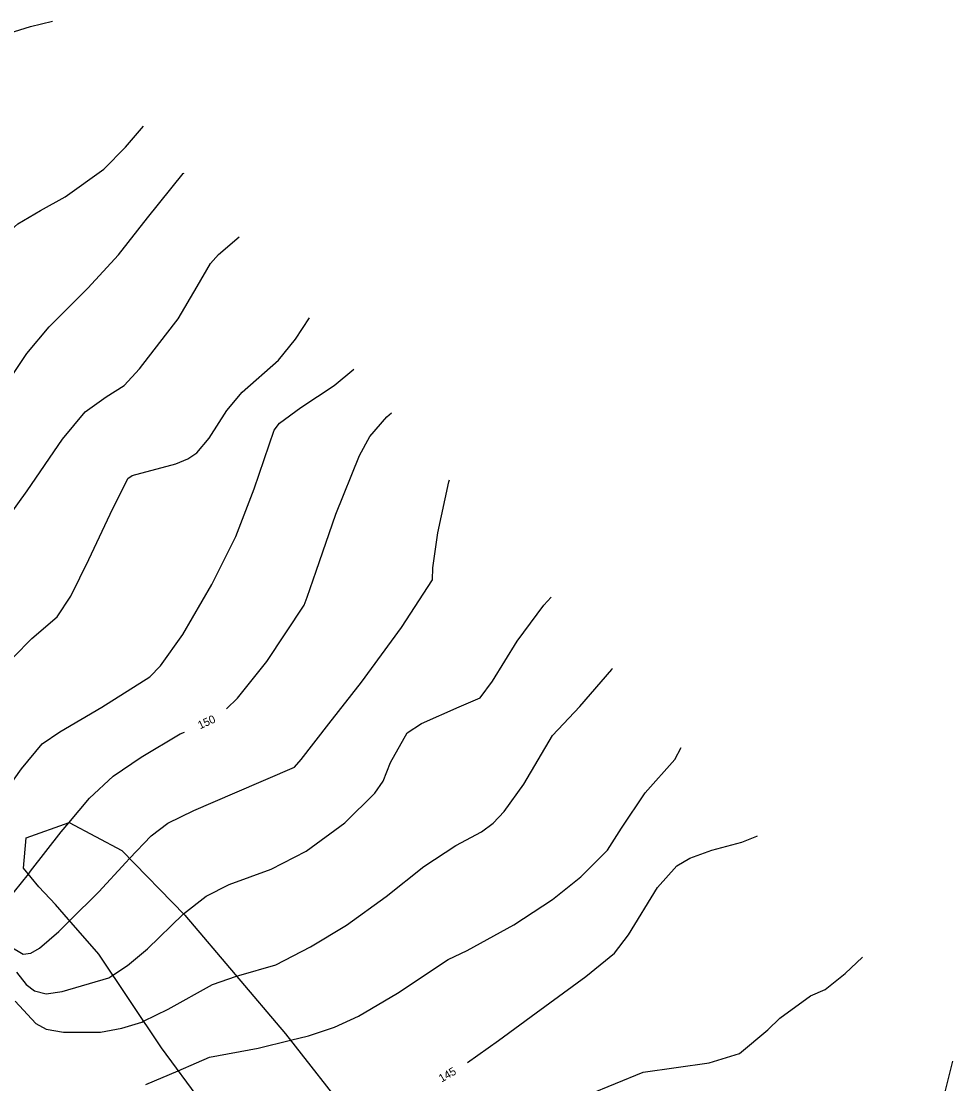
# Model space of a CAD drawing. Extents: x 1467615 to 2003689, y 770235 to 1108726.
# Drawn here: x 2000704.8 to 2000937.1, y 773522.7 to 773787.7 of the extents above; entities that cross this region are included whole.
import ezdxf

# ---------------------------------------------------------------- set-up
doc = ezdxf.new("R2010")
doc.units = 0
for name, color, linetype in [('RD_DTM_Major1', 7, 'Continuous'), ('RD_DTM_Major1_Lbl', 7, 'Continuous'), ('RD_DTM_Major2', 7, 'Continuous'), ('RD_DTM_Minor1', 7, 'Continuous'), ('RD_DTM_Minor2', 7, 'Continuous'), ('RD_DTM_Obscure', 7, 'Continuous')]:
    doc.layers.add(name, color=color, linetype=linetype)

msp = doc.modelspace()

# ---------------------------------------------------------------- linework, layer by layer
at = {"layer": 'RD_DTM_Major1'}
for points in [[(2000670.71, 773684.15), (2000672.17, 773685.91), (2000676.92, 773693.59), (2000683.08, 773706.51), (2000686.44, 773711.87), (2000690.3, 773716.17), (2000695.1, 773720.9), (2000696.9, 773724.25), (2000699.75, 773732.32), (2000701.53, 773734.98), (2000703.98, 773737.23), (2000709.63, 773740.52), (2000715.78, 773743.93), (2000725.45, 773750.81), (2000730.87, 773756.33), (2000735.33, 773761.55)], [(2000756.03, 773616.27), (2000758.78, 773618.87), (2000766.05, 773628.08), (2000775.35, 773642.1), (2000776.13, 773644.05), (2000778.35, 773650.59), (2000783.3, 773664.81), (2000789.2, 773679.42), (2000791.78, 773684.13), (2000796.03, 773689.04), (2000797.18, 773690.06)], [(2000716.71, 773587.83), (2000721.89, 773593.94), (2000727.8, 773599.46), (2000734.75, 773604.17), (2000744.49, 773609.96), (2000745.51, 773610.43)], [(2000816.14, 773528.05), (2000823.88, 773533.49), (2000833.24, 773540.36), (2000845.63, 773549.46), (2000852.81, 773555.27), (2000856.25, 773559.88), (2000863.5, 773571.7), (2000868.29, 773577.04), (2000871.59, 773578.98), (2000877.08, 773580.98), (2000884.56, 773582.95), (2000888.26, 773584.45), (2000888.44, 773584.58)], [(2000699.64, 773566.36), (2000706.61, 773575)]]:
    msp.add_lwpolyline(points, dxfattribs=at)
at = {"layer": 'RD_DTM_Major2'}
msp.add_lwpolyline([(2000706.61, 773575), (2000707.18, 773575.71), (2000714.77, 773585.54), (2000716.71, 773587.83)], dxfattribs=at)
at = {"layer": 'RD_DTM_Minor1'}
for points in [[(2000696.38, 773783.12), (2000707.12, 773786.46), (2000712.66, 773787.75)], [(2000697.43, 773691.84), (2000706.25, 773704.87), (2000711.83, 773711.5), (2000721.41, 773721.17), (2000729.09, 773729.52), (2000736.32, 773738.72), (2000745.25, 773749.73), (2000745.44, 773749.87)], [(2000698.45, 773659.69), (2000706.28, 773670.58), (2000715.11, 773683.52), (2000720.81, 773690.35), (2000725.99, 773694.07), (2000730.51, 773696.88), (2000734.32, 773701.04), (2000740.84, 773709.42), (2000744.01, 773713.51), (2000748.7, 773721.6), (2000752, 773727.3), (2000753.99, 773729.53), (2000759.17, 773733.99)], [(2000702.89, 773629.12), (2000707.51, 773633.81), (2000713.82, 773639.18), (2000717.19, 773644.33), (2000721.72, 773653.5), (2000726.98, 773664.78), (2000731.4, 773673.69), (2000732.51, 773674.43), (2000743.38, 773677.34), (2000746.36, 773678.61), (2000748.63, 773680.1), (2000751.7, 773683.73), (2000756.07, 773690.63), (2000759.89, 773695.24), (2000768.98, 773703.22), (2000773.2, 773708.45), (2000776.7, 773713.73)], [(2000696.65, 773589.8), (2000704.91, 773601.24), (2000710.03, 773607.53), (2000714.49, 773610.48), (2000724.93, 773616.66), (2000736.92, 773624.25), (2000739.58, 773626.96), (2000745.1, 773634.78), (2000752.38, 773647.22), (2000758.31, 773659.2), (2000762.91, 773671.14), (2000767.89, 773685.75), (2000769.27, 773687.52), (2000774.57, 773691.39), (2000782.91, 773696.89), (2000787.79, 773700.92)], [(2000731.87, 773578.94), (2000737.2, 773584.55), (2000741.4, 773587.69), (2000747.86, 773590.88), (2000758.11, 773595.31), (2000772.96, 773601.67), (2000774.63, 773603.63), (2000781.53, 773612.5), (2000789.67, 773622.92), (2000799.66, 773636.48), (2000807.37, 773648.42), (2000807.48, 773651.43), (2000808.71, 773660.13), (2000811.49, 773672.89), (2000811.64, 773673.35)], [(2000745.34, 773565.07), (2000750.98, 773569.54), (2000756.66, 773572.38), (2000767.13, 773576.27), (2000775.92, 773580.76), (2000785.51, 773587.78), (2000793.04, 773595.16), (2000795.1, 773598.17), (2000796.95, 773602.87), (2000801.1, 773610.24), (2000804.63, 773612.59), (2000814.03, 773616.7), (2000819.32, 773619.01), (2000822.35, 773623.15), (2000828.5, 773633.14), (2000835.19, 773642.06), (2000836.95, 773644.1)], [(2000758.53, 773549.55), (2000759.06, 773549.74), (2000768.33, 773552.39), (2000776.95, 773556.86), (2000785.92, 773562.27), (2000795.81, 773569.44), (2000805.24, 773576.92), (2000813.2, 773582.12), (2000819.62, 773585.54), (2000822.5, 773587.69), (2000825.28, 773590.61), (2000830.14, 773597.47), (2000837.33, 773609.57), (2000844.15, 773616.85), (2000852.14, 773626.05), (2000852.31, 773626.34)], [(2000771.99, 773533.55), (2000776.5, 773534.63), (2000782.98, 773536.84), (2000788.94, 773539.54), (2000798.66, 773545.31), (2000811.26, 773553.74), (2000816.01, 773555.93), (2000827.64, 773562.39), (2000837.28, 773568.63), (2000844.42, 773574.31), (2000851.03, 773580.94), (2000854.56, 773586.5), (2000860.39, 773595.28), (2000867.84, 773603.62), (2000869.41, 773606.58)], [(2000698.23, 773559.19), (2000705.34, 773555.04), (2000707.22, 773555.32), (2000709.38, 773556.5), (2000714.17, 773560.67), (2000716.89, 773563.36)], [(2000796.83, 773501.47), (2000797.99, 773501.8), (2000802.24, 773504.61), (2000806.43, 773507.27), (2000813.01, 773509.48), (2000825.34, 773512.91), (2000841.79, 773517.87), (2000846.16, 773519.97), (2000859.89, 773525.58), (2000876.35, 773527.93), (2000883.99, 773530.28), (2000891.05, 773536.16), (2000893.99, 773539.1), (2000901.66, 773544.65), (2000905.31, 773546.23), (2000910.32, 773550.2), (2000914.62, 773554.32)], [(2000703.67, 773550.51), (2000706.07, 773547.44), (2000708.13, 773545.88), (2000711.08, 773545.17), (2000715.01, 773545.76), (2000726.64, 773549.11), (2000727.68, 773549.8)], [(2000703.32, 773543.3), (2000708.44, 773537.74), (2000711.06, 773536.32), (2000715.39, 773535.59), (2000724.56, 773535.59), (2000729.94, 773536.56), (2000734.92, 773538.11), (2000735.34, 773538.32)], [(2000810.42, 773484.25), (2000810.76, 773484.38), (2000822.72, 773487.9), (2000837.33, 773490.72), (2000845.47, 773492.85), (2000852.83, 773495.24), (2000856.14, 773495.89), (2000859.21, 773495.88), (2000865.74, 773494.16), (2000880.04, 773489.27), (2000893.7, 773485.23), (2000900.89, 773485.06), (2000905.01, 773485.42), (2000909.62, 773486.48), (2000914.34, 773488.63), (2000918.84, 773492.05), (2000922.89, 773496.21), (2000930.59, 773506.31), (2000932.18, 773509.25), (2000935.05, 773520.02), (2000937.13, 773528.31)], [(2000735.87, 773522.49), (2000743.99, 773525.95)]]:
    msp.add_lwpolyline(points, dxfattribs=at)
at = {"layer": 'RD_DTM_Minor2'}
for points in [[(2000716.89, 773563.36), (2000724.2, 773570.58), (2000730.9, 773577.93), (2000731.87, 773578.94)], [(2000727.68, 773549.8), (2000731.3, 773552.2), (2000736.33, 773556.38), (2000745.22, 773564.98), (2000745.34, 773565.07)], [(2000735.34, 773538.32), (2000741.5, 773541.34), (2000752.55, 773547.43), (2000758.53, 773549.55)], [(2000743.99, 773525.95), (2000748.54, 773527.89), (2000751.78, 773529.31), (2000763.94, 773531.61), (2000771.99, 773533.55)]]:
    msp.add_lwpolyline(points, dxfattribs=at)
at = {"layer": 'RD_DTM_Obscure'}
msp.add_lwpolyline([(2000749.85, 773518.03), (2000739.78, 773531.64), (2000724.21, 773555.01), (2000715.52, 773564.91), (2000713.38, 773567.41), (2000709.24, 773571.8), (2000705.41, 773576.47), (2000706.08, 773584.09), (2000716.76, 773587.85), (2000729.94, 773580.93), (2000745.63, 773564.78), (2000770.7, 773535.19), (2000787.27, 773514.02)], dxfattribs=at)

# ---------------------------------------------------------------- texts
at = {"layer": 'RD_DTM_Major1_Lbl'}
for s, rotation, p in [('150', 24.5131, (2000749.42, 773611.11)), ('145', 30.4769, (2000809.68, 773522.99))]:
    msp.add_text(s, height=2, rotation=rotation, dxfattribs=at).set_placement(p)

doc.saveas('drawing.dxf')
